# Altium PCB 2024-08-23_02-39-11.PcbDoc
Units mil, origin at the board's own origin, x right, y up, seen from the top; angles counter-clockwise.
Board outline 3261 x 2832 mil, 4 copper layers (Top Layer, MidLayer1, MidLayer2, Bottom Layer); 25 components, 14 nets, 72 pads, 147 vias.
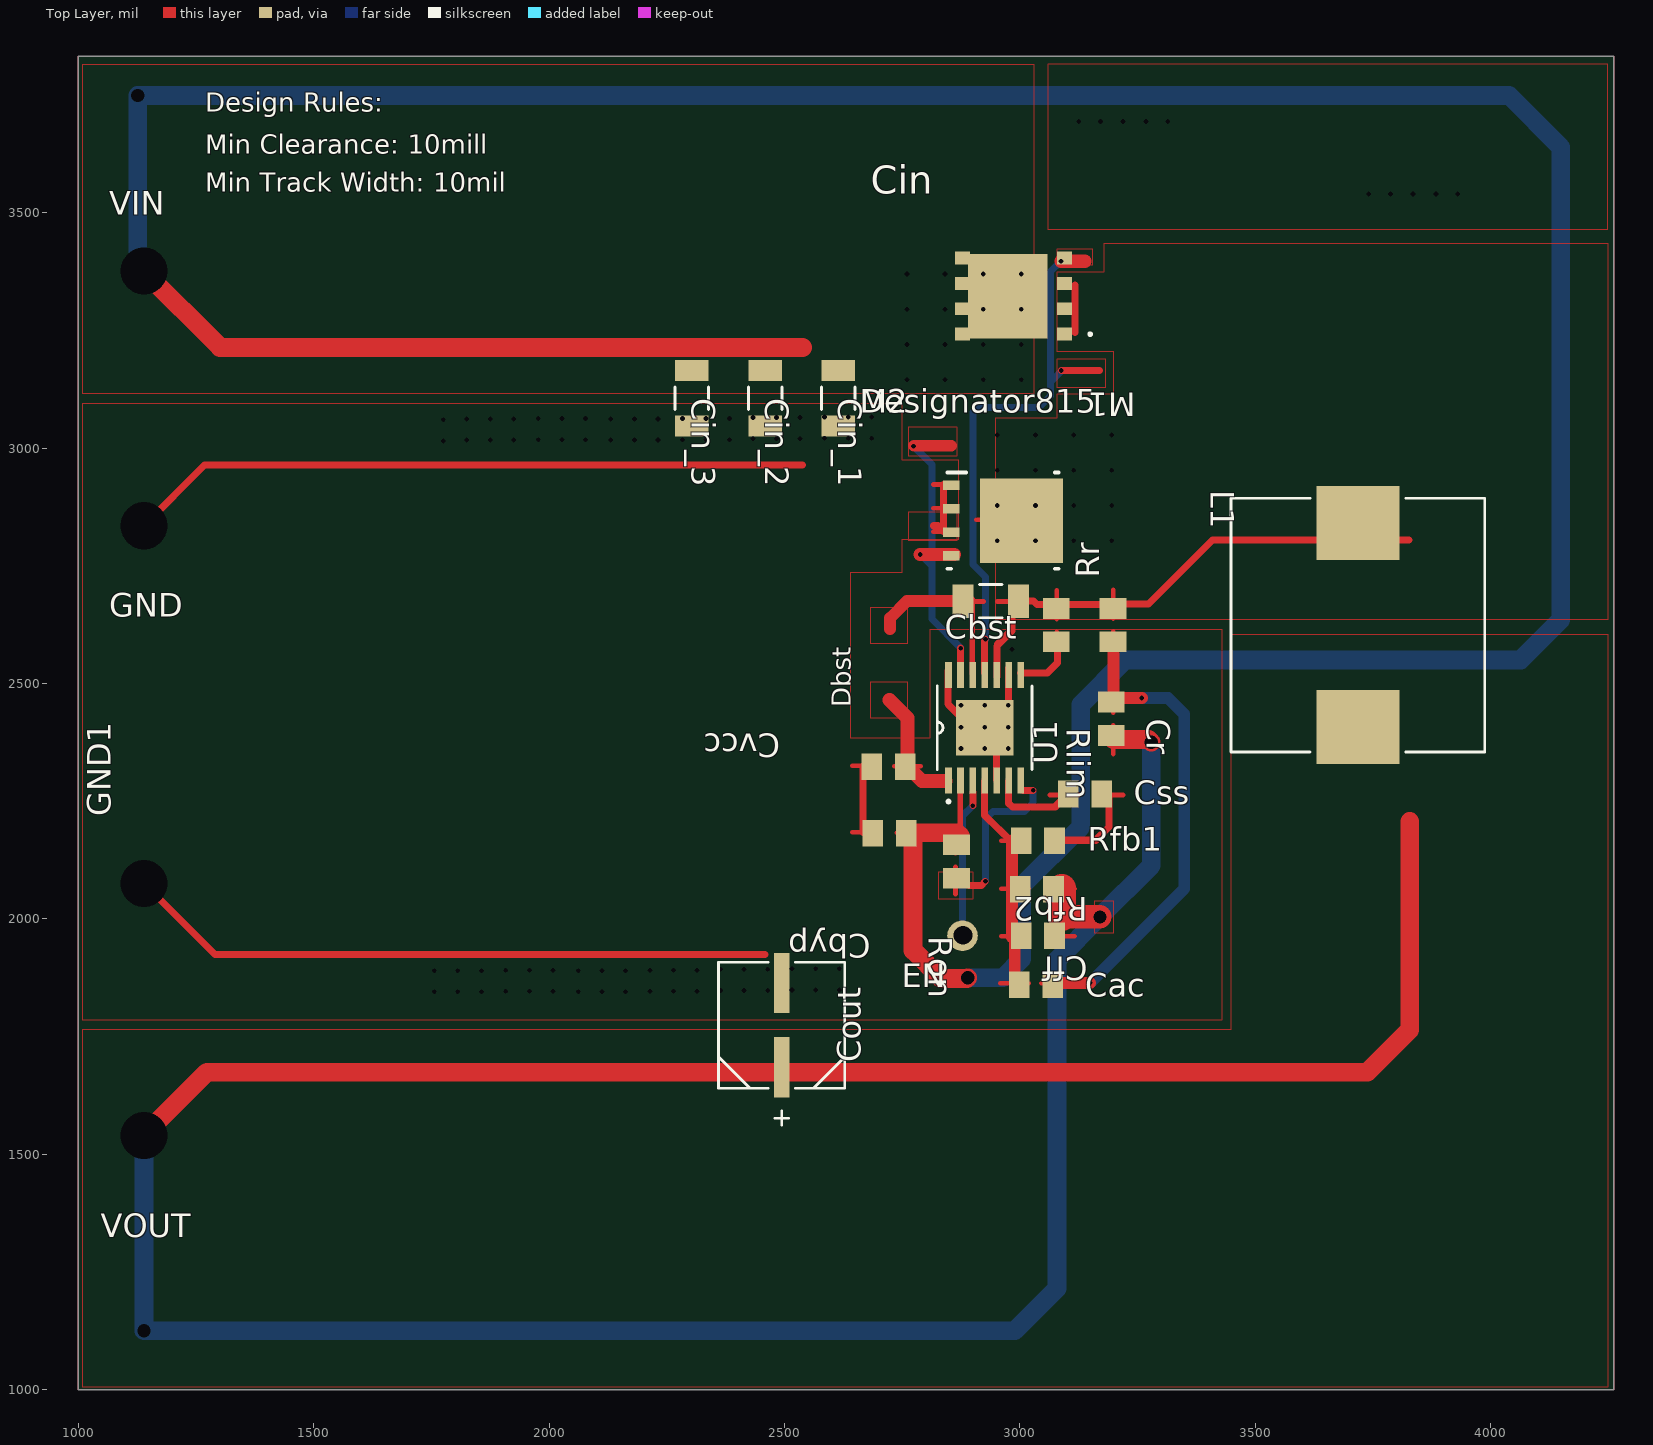
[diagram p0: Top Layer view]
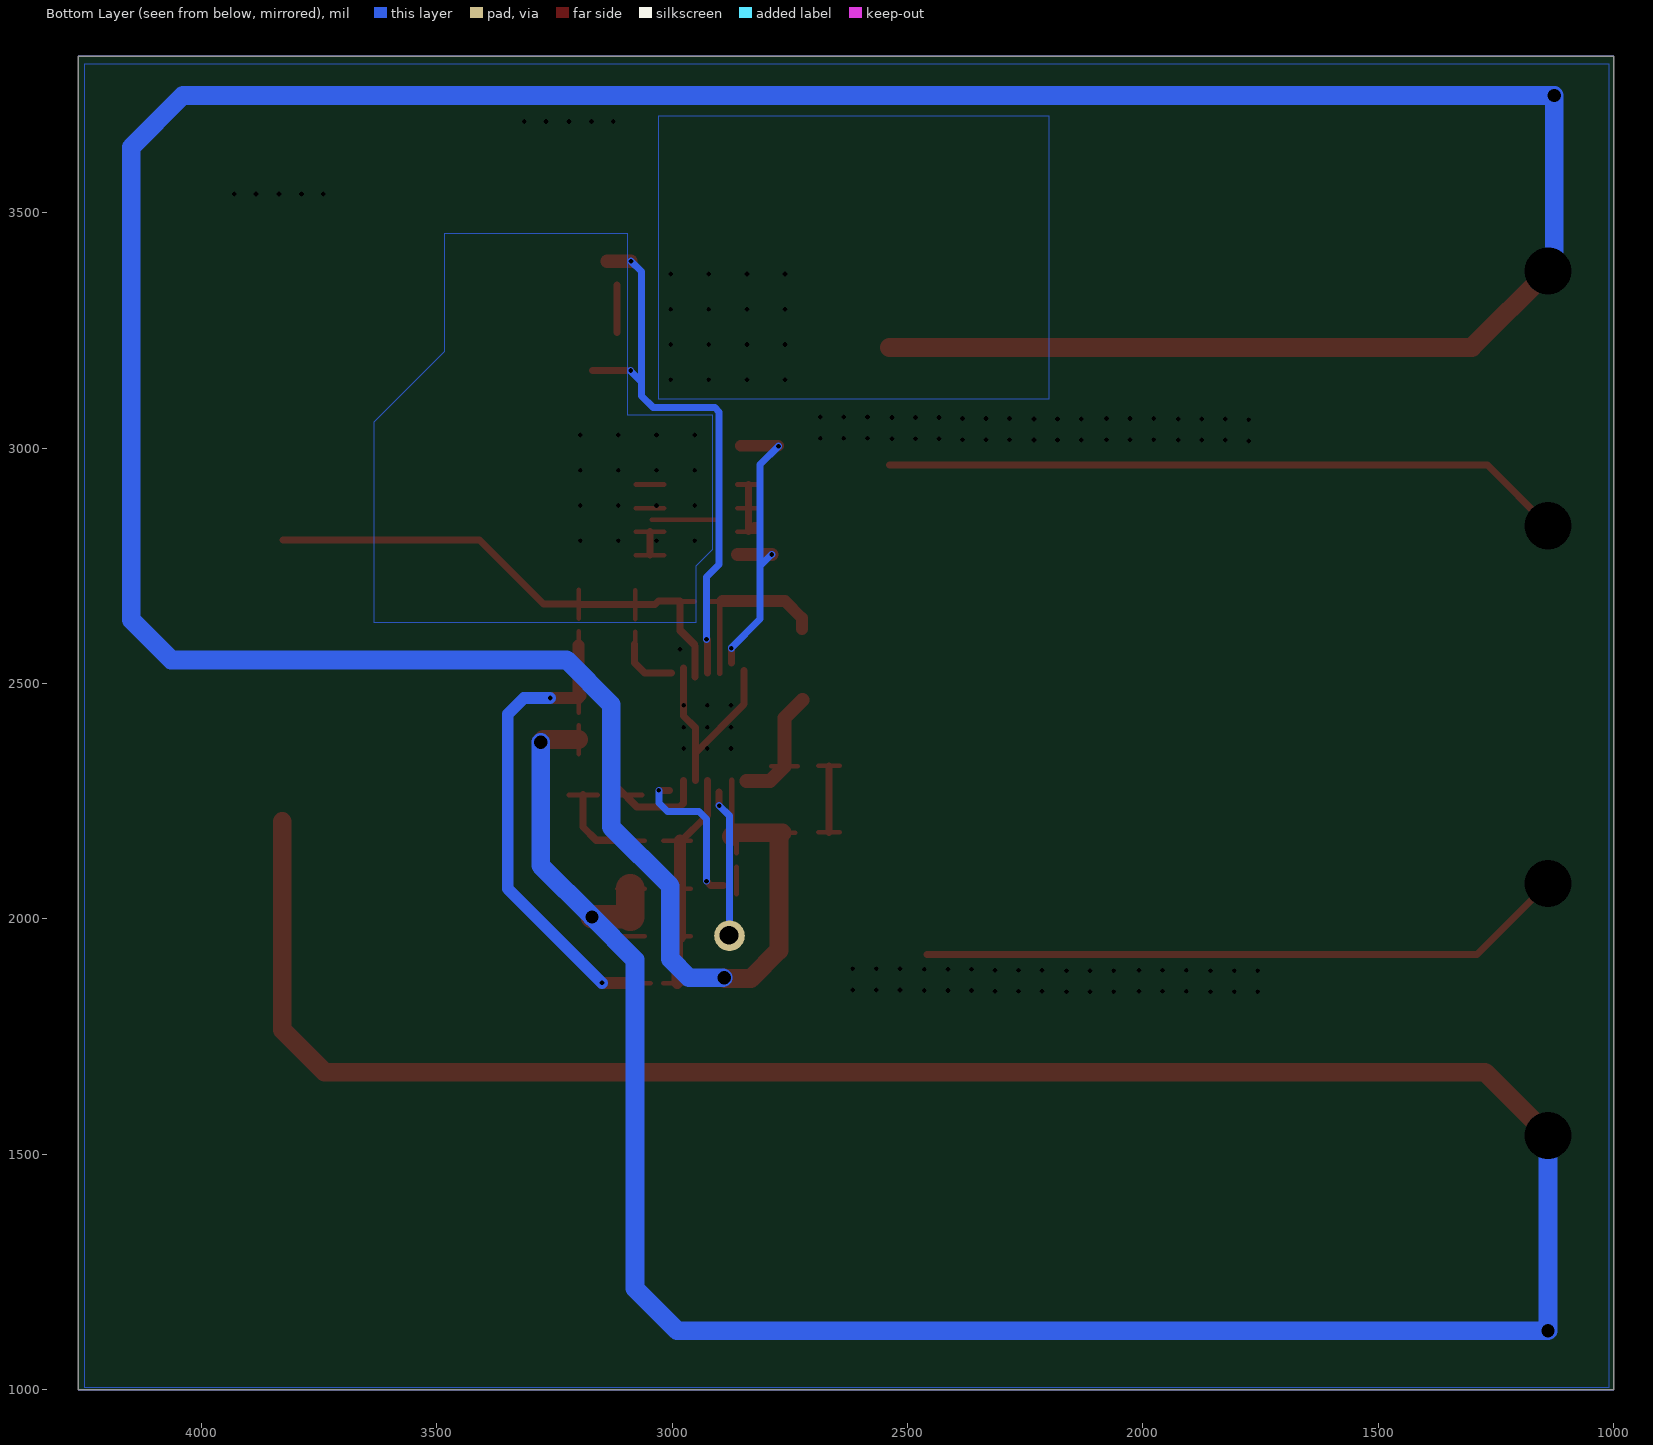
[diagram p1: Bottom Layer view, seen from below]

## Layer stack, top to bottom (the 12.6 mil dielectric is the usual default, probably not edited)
Top Layer: signal copper 1.4
Dielectric: core 12.6, FR-4, Dk 4.8
MidLayer1: signal copper 1.4
Dielectric: prepreg 12.6, FR-4, Dk 4.8
MidLayer2: signal copper 1.4
Dielectric: core 12.6, FR-4, Dk 4.8
Bottom Layer: signal copper 1.4

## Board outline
1000,1000 4261,1000 4261,3832 1000,3832

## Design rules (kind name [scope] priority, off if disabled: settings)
PlaneConnect [All] p0: scope1count=1 scope1_0_kind=Board scope1_0_value=Board scope2count=1 scope2_0_kind=Board scope2_0_value=Board commentlength=0 planeconnectstyle=Direct reliefexpansion=20 reliefentries=4 reliefconductorwidth=10 reliefairgap=10
PlaneConnect [All] p1: planeconnectstyle=Direct reliefexpansion=20 reliefentries=4 reliefconductorwidth=10 reliefairgap=10
PolygonConnect [All] p0: scope1count=1 scope1_0_kind=Board scope1_0_value=Board scope2count=1 scope2_0_kind=Board scope2_0_value=Board commentlength=0 connectstyle=Direct reliefconductorwidth=10 reliefentries=4 polygonreliefangle="90 Angle"
PolygonConnect [All] p1: connectstyle=Direct reliefconductorwidth=10 reliefentries=4 polygonreliefangle="90 Angle"

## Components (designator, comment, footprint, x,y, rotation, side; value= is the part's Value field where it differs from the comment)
Cac "" 0805 3034,1860 r0 top
Cbst "" 1206 2938,2675 r0 top
Cbyp "" 0805 2723,2182 r180 top
Cff "" 0805 3038,1964 r180 top
Cin_1 "" 1206 2614,3106 r270 top
Cin_2 "" 1206 2459,3106 r270 top
Cin_3 "" 1206 2303,3106 r270 top
Cout "" CAPSMT_62_C10 2494,1774 r90 top
Cr "" 0805 3194,2425 r270 top
Css "" 0805 3138,2265 r0 top
Cvcc "" 0805 2721,2323 r180 top
EN "" TP-1502 2878,1964 r0 top
GND "" TP-1502 1138,2834 r0 top
GND1 "" TP-1502 1138,2073 r90 top
L1 "" SRP1270 3718,2624 r270 top
M1 "" TRANS_NexFET_Q5A 2986,3323 r180 top
M2 "" DQJ0008A 2964,2846 r0 top
Rfb1 "" 0805 3038,2166 r0 top
Rfb2 "" 0805 3036,2063 r180 top
Rlim "" 0805 3077,2624 r270 top
Ron "" 0805 2865,2122 r270 top
Rr "" 0805 3198,2624 r90 top
U1 "" MXA14A 2925,2406 r90 top
VIN "" TP-1502 1138,3375 r0 top
VOUT "" TP-1502 1138,1538 r0 top

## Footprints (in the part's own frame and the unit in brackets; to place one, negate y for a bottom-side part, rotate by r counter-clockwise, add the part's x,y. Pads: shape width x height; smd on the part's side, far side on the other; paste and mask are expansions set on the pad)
0805 [mil]
  rect 44x57 smd: 1(-35.5,0) 2(35.5,0)
1206 [mil]
  rect 44x71 smd: 1(-59,0) 2(59,0)
  silkscreen extent -24,-36 24,36
CAPSMT_62_C10 [mil]
  rect 128x32 smd: 1(-89.5,0) 2(89.5,0)
  silkscreen extent -212,-134 134,134
DQJ0008A [mm]
  rect 0.91x0.51 smd: 1(-2.795,1.905) 2(-2.795,0.635) 3(-2.795,-0.635) 4(-2.795,-1.905) 5(2.795,-1.905) 6(2.795,-0.635) 7(2.795,0.635) 8(2.795,1.905)
  rect 4.49x4.57 smd: 9(1.005,0)
  silkscreen extent -3,-2.6 3,2.6
MXA14A [mil]
  rect 56x14 smd: 1(-112,76.77) 2(-112,51.18) 3(-112,25.59) 4(-112,0) 5(-112,-25.59) 6(-112,-51.18) 7(-112,-76.77) 8(112,-76.77) 9(112,-51.18) 10(112,-25.59) 11(112,0) 12(112,25.59) 13(112,51.18) 14(112,76.77)
  rect 118x122 smd: 15(0,0)
  silkscreen extent -160,-100 88,100
SRP1270 [mil]
  rect 157.5x177 smd: 1(-216.75,0) 2(216.75,0)
  silkscreen extent -270,-270 270,270
TP-1502 [mil]
  round 65 hole 32: 1(0,0)
TRANS_NexFET_Q5A [mm]
  rect 0.8x0.7 smd: 1(-2.752,2.055) 2(-2.752,0.685) 3(-2.752,-0.685) 4(-2.752,-2.055) 5(2.752,-2.055) 6(2.752,-0.685) 7(2.752,0.685) 8(2.752,2.055)
  rect 4.3x4.56 smd: 9(0.3,0)
  silkscreen extent -4.22,1.98 -4.07,2.13

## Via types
v1: diameter 0, hole 10, Top Layer to Bottom Layer, 137 vias
v2: diameter 0, hole 28, Top Layer to Bottom Layer, 5 vias
v3: diameter 0, hole 100, Top Layer to Bottom Layer, 4 vias
v4: diameter 0, hole 40, Top Layer to Bottom Layer, 1 vias

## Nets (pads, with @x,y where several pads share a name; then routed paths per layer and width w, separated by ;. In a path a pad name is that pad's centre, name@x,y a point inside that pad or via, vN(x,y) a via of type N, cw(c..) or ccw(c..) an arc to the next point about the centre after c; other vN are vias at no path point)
0: Cbyp.2 Cin_1.2 Cin_2.2 Cin_3.2 Cout.2 Css.2 Cvcc.2 GND1.1 GND.1 M2.1 M2.2 M2.3 Rfb1.2 U1.5 U1.9 U1.14 U1.15 | length 4097
  Top Layer w10: 2644,2184 Cbyp.2@2689,2184 ; 2644,2325 Cvcc.2@2689,2325 ; 2816,2822.5 M2.3@2861,2822.5 ; 2816,2872.5 M2.2@2861,2872.5 ; 2816,2922.5 M2.1@2861,2922.5 ; Rfb1.2@3058,2166 3116,2166 ; Css.2@3158,2263 3219,2263
  Top Layer w15: v3(1139,2075) 1290,1924 2458,1924 ; v3(1139,2835) 1268,2964 2538,2964 ; Cbyp.2@2667,2184 Cvcc.2@2667,2325 ; 2816,2835 2826,2835 2838,2823 2838,2873 M2.1@2838,2923 ; U1.14@2847,2528 2847,2456 U1.15@2950,2352 ; U1.5@2950,2294 U1.15@2950,2352 ; U1.9@2976,2533 2976,2431 2950,2406 U1.15@2950,2352 ; Rfb1.2@3087,2167 3161,2167 3189,2195 Css.2@3189,2264
  other v1: 1756,1845 1806,1845 1856,1845 2062,1845 2112,1845 2162,1845 1908,1846 1958,1846 2008,1846 2214,1846 2264,1846 2314,1846 2364,1848 2414,1848 2464,1848 2516,1849 2566,1849 2616,1849 1756,1890 1806,1890 1856,1890 2062,1890 2112,1890 2162,1890 1908,1891 1958,1891 2008,1891 2214,1891 2264,1891 2314,1891 2364,1893 2414,1893 2464,1893 2516,1894 2566,1894 2616,1894 2875,2362 2925,2362 2975,2362 2875,2407 2925,2407 2975,2407 2875,2454 2925,2454 2975,2454 2983,2573 1775,3015 1825,3017 1875,3017 1925,3017 2131,3017 2181,3017 2231,3017 1977,3018 2027,3018 2077,3018 2283,3018 2333,3018 2383,3018 2433,3020 2483,3020 2533,3020 2585,3021 2635,3021 2685,3021 1775,3060 1825,3062 1875,3062 1925,3062 2131,3062 2181,3062 2231,3062 1977,3063 2027,3063 2077,3063 2283,3063 2333,3063 2383,3063 2433,3065 2483,3065 2533,3065 2585,3066 2635,3066 2685,3066 3741,3540 3787,3540 3835,3540 3884,3540 3930,3540 3125,3694 3171,3694 3219,3694 3268,3694 3314,3694
1: Cbyp.1 Cin_1.1 Cin_2.1 Cin_3.1 M1.5 M1.6 M1.7 M1.8 M1.9 Ron.1 U1.2 VIN.1 | length 8469.1
  Top Layer w10: Cbyp.1@2738,2183 2794,2183 ; Ron.1@2863,2140 2863,2198
  Top Layer w12: 2866,2183 2873,2190 U1.2@2873,2294
  Top Layer w40: v3(1139,3376) 1301,3214 2538,3214 ; Ron.1@2874,2175 2866,2183 2766,2183 2769,2180 2773,2180 2773,1933 2833,1873 2887,1873 v2(2889,1875)
  Bottom Layer w40: VIN.1@1139,3375 1126,3388 v2(1126,3749) 4039,3749 4149,3639 4149,2635 4064,2550 3224,2550 3129,2455 3129,2195 3004,2070 3004,1915 2964,1875 2892,1875
  other v1: 2760,3145 2841,3145 2922,3145 3003,3145 2760,3220 2841,3220 2922,3220 3003,3220 2760,3295 2841,3295 2922,3295 3003,3295 2760,3370 2841,3370 2922,3370 3003,3370
2: Ron.2 U1.7 | length 393.4
  Top Layer w10: 2863,2052 2863,2110
  Top Layer w15: Ron.2@2891,2071 2918,2071 2926,2079 ; U1.7@3005,2273 v1(3028,2273)
  Bottom Layer w15: v1(2927,2080) 2927,2212 2943,2228 3010,2228 3028,2246 v1(3028,2273)
3: Cac.1 Cff.2 Rfb1.1 Rfb2.2 U1.4 | length 697.7
  Top Layer w10: 2958,1863 Cac.1@3019,1863 ; 2960,1963 Cff.2@3018,1963 ; 2960,2064 Rfb2.2@3018,2064 ; 2960,2166 Rfb1.1@3018,2166
  Top Layer w15: U1.4 2925,2293 2925,2220 Rfb1.1@2983,2163
  Top Layer w25: Rfb1.1@2983,2167 2983,2163 2983,1961 Cff.2@2984,1960 ; Cac.1@2989,1864 Cff.2@2989,1964
4: Cbst.2 L1.1 M1.1 M1.2 M1.3 M2.5 M2.6 M2.7 M2.8 M2.9 Rlim.1 Rr.2 U1.10 | length 1829.7
  Top Layer w10: 2907,2847.5 M2.9@3043,2847.5 ; 2952,2674 Cbst.2@3013,2674 ; M2.9@3017,2772.5 M2.5@3077,2772.5 ; M2.9@3017,2822.5 M2.6@3077,2822.5 ; M2.9@3017,2872.5 M2.7@3077,2872.5 ; M2.9@3017,2922.5 M2.8@3077,2922.5 ; 3078,2637 3078,2698 ; Rr.2@3198,2638 3198,2699
  Top Layer w15: U1.10@2951,2514 2951,2580 2983,2612 2983,2615 ; 2952,2584 2983,2615 ; M2.9@3047,2773 M2.9@3047,2823 ; 3117,3246 3117,3296 3117,3346 ; 3826,2805 3409,2805 3273,2669 3199,2669 3198,2668 3079,2668 3036,2668 3029,2675 2983,2675 2983,2615
  other v1: 2952,2803 3033,2803 3114,2803 3195,2803 2952,2878 3033,2878 3114,2878 3195,2878 2952,2953 3033,2953 3114,2953 3195,2953 2952,3028 3033,3028 3114,3028 3195,3028
5: Cff.1 Cout.1 Cr.2 L1.2 Rfb2.1 VOUT.1 | length 7261.4
  Top Layer w10: Cff.1@3058,1963 3116,1963 ; Rfb2.1@3058,2064 3116,2064 ; 3198,2350 Cr.2@3198,2411
  Top Layer w40: v3(1139,1540) 1273,1674 2458,1674 3738,1674 3828,1764 3828,2207 ; Cr.2@3199,2381 3273,2381 v2(3279,2375)
  Top Layer w50: 3089,2004 v2(3170,2004)
  Top Layer w60: 3089,2004 Rfb2.1@3089,2065
  Bottom Layer w40: v3(1139,1540) v2(1139,1125) 2989,1125 3079,1215 3079,1913 v2(3170,2004) 3279,2113 v2(3279,2375)
6: M2.4 U1.13 | length 734.4
  Top Layer w10: 2816,2772.5 M2.4@2861,2772.5
  Top Layer w15: U1.13@2874,2544 v1(2874,2575)
  Top Layer w25: 2775,3005 2854,3005
  Top Layer w28: v1(2788,2774) M2.4@2861,2774
  Bottom Layer w15: v1(2774,3004) 2813,2965 2813,2750 ; v1(2788,2774) 2789,2774 2813,2750 ; 2874,2574 2874,2576 2813,2637 2813,2750
7: Cbst.1 U1.12 | length 418.1
  Top Layer w10: Cbst.1@2867,2674 2923,2674
  Top Layer w12: Cbst.1@2893,2675 2899,2668 U1.12@2899,2522
  Top Layer w25: 2724,2616 2724,2639 2760,2675 Cbst.1@2893,2675
8: M1.4 U1.11 | length 1204.9
  Top Layer w15: U1.11@2925,2522 2925,2593 2926,2594 ; v1(3088,3165) 3169,3165
  Top Layer w28: v1(3087,3397) 3138,3397
  Bottom Layer w15: v1(2927,2594) 2927,2726 2900,2753 2900,3077 2909,3086 3040,3086 3065,3111 3065,3375 v1(3087,3397) ; 3066,3142 3088,3164 v1(3088,3165)
9: Rlim.2 U1.8 | length 189.1
  Top Layer w10: 3078,2549 Rlim.2@3078,2610
  Top Layer w15: U1.8@3001,2522 3058,2522 3080,2544 Rlim.2@3080,2584
10: Css.1 U1.6 | length 268.2
  Top Layer w10: 3064,2263 3125,2263
  Top Layer w15: U1.6@2976,2294 2976,2245 2984,2238 3075,2238 Css.1@3115,2278
11: Cvcc.1 U1.1 | length 304.6
  Top Layer w10: 2733,2324 2789,2324
  Top Layer w30: 2723,2465 2761,2427 Cvcc.1@2761,2326 ; Cvcc.1@2761,2324 2792,2293 U1.1@2842,2293
18: EN.1 U1.3 | length 318.1
  Top Layer w15: 2900,2241 U1.3@2900,2269
  Bottom Layer w15: EN.1@2878,1960 2878,2219 2900,2241
  other v1: 2900,2240
  other v4: 2879,1965
25: Cac.2 Cr.1 Rr.1 | length 1182
  Top Layer w10: 3046,1863 3107,1863 ; 3198,2438 3198,2499 ; 3198,2550 3198,2611
  Top Layer w25: Cac.2@3077,1864 v1(3149,1864) ; Cr.1@3194,2474 3199,2479 Rr.1@3199,2581 ; Cr.1@3199,2469 v1(3259,2469)
  Bottom Layer w25: v1(3149,1864) 3349,2064 3349,2435 3315,2469 v1(3259,2469)

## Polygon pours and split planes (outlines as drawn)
2 on Top Layer " " (solid, pour order 0): 2827,2042 2827,2100 2900,2100 2900,2042
11 on Top Layer " " (solid, pour order 1): 2683,2426 2683,2504 2761,2504 2761,2426
7 on Top Layer " " (solid, pour order 2): 2683,2584 2683,2662 2761,2662 2761,2584
6 on Top Layer " " (solid, pour order 3): 2764,2983 2764,3045 2866,3045 2866,2983
8 on Top Layer " " (solid, pour order 4): 3079,3128 3079,3190 3181,3190 3181,3128
8 on Top Layer " " (solid, pour order 5): 3079,3388 3079,3423 3154,3423 3154,3388
1 on Top Layer " " (solid, pour order 6): 2906,3244 2906,3397 3056,3397 3056,3244
4 on Top Layer " " (solid, pour order 7): 2949,2635 2949,3065 3079,3065 3079,3115 3199,3115 3199,3205 3079,3205 3079,3375 3179,3375 3179,3435 4249,3435 4249,2635
1 on Top Layer " " (solid, pour order 8): 1009,3815 3029,3815 3029,3115 1009,3115
5 on Top Layer " " (solid, pour order 9): 1009,1005 1009,1765 3449,1765 3449,2605 4249,2605 4249,1005
5 on Top Layer " " (solid, pour order 10): 3158,2037 3158,1971 3199,1971 3199,2037
0 on Top Layer " " (solid, pour order 13): 2764,2803 2764,2865 2866,2865 2866,2803
0 on Top Layer " " (solid, pour order 14): 3059,3815 3059,3465 4249,3465 4249,3815
0 on Top Layer " " (solid, pour order 15): 1009,3095 2749,3095 2749,2975 2869,2975 2869,2805 2749,2805 2749,2735 2639,2735 2639,2385 2809,2385 2809,2615 3429,2615 3429,1785 1009,1785
4 on Bottom Layer " " (solid, pour order 11): 3094,3455 3484,3455 3484,3205 3634,3055 3634,2630 2949,2630 2949,2750 2914,2785 2914,3070 3094,3070 3094,3390
1 on Bottom Layer " " (solid, pour order 12): 2199,3705 3029,3705 3029,3105 2199,3105
0 on Bottom Layer " " (solid, pour order 16): 1009,1005 1009,3815 4249,3815 4249,1005
no net on Top Paste "Top Layer-No Net" (solid, remove dead copper): 2893.38,3228.31 2893.38,3255.87 2861.89,3255.87 2861.89,3228.31
no net on Top Solder "Top Layer-No Net" (solid, remove dead copper): 3110.11,3228.32 3110.11,3255.87 3078.62,3255.87 3078.62,3228.32
no net on Top Solder "Top Layer-No Net" (solid, remove dead copper): 3110.11,3282.25 3110.11,3309.81 3078.62,3309.81 3078.62,3282.25
no net on Top Solder "Top Layer-No Net" (solid, remove dead copper): 3110.11,3336.19 3110.11,3363.75 3078.62,3363.75 3078.62,3336.19
no net on Top Solder "Top Layer-No Net" (solid, remove dead copper): 3110.11,3390.13 3110.11,3417.69 3078.62,3417.69 3078.62,3390.13
no net on Top Solder "Top Layer-No Net" (solid, remove dead copper): 2893.38,3390.13 2893.38,3417.68 2861.89,3417.68 2861.89,3390.13
no net on Top Solder "Top Layer-No Net" (solid, remove dead copper): 2893.38,3336.19 2893.38,3363.75 2861.89,3363.75 2861.89,3336.19
no net on Top Solder "Top Layer-No Net" (solid, remove dead copper): 2893.38,3282.25 2893.38,3309.81 2861.89,3309.81 2861.89,3282.25
no net on Top Solder "Top Layer-No Net" (solid, remove dead copper): 2893.38,3228.31 2893.38,3255.87 2861.89,3255.87 2861.89,3228.31
no net on Top Solder "Top Layer-No Net" (solid, remove dead copper): 2893.48,3233.24 3062.77,3233.24 3062.77,3412.76 2893.48,3412.76
no net on Top Solder "Top Layer-No Net" (solid, remove dead copper): 3052.58,2812.93 3061.44,2812.93 3061.44,2829.07 3052.58,2829.07
no net on Top Solder "Top Layer-No Net" (solid, remove dead copper): 3052.58,2762.93 3061.44,2762.93 3061.44,2779.07 3052.58,2779.07
no net on Top Solder "Top Layer-No Net" (solid, remove dead copper): 3052.58,2912.93 3061.44,2912.93 3061.44,2929.07 3052.58,2929.07
no net on Top Solder "Top Layer-No Net" (solid, remove dead copper): 3052.58,2862.93 3061.44,2862.93 3061.44,2879.07 3052.58,2879.07
no net on Top Paste "Top Layer-No Net" (solid, remove dead copper): 2917.94,2823.36 2917.94,2868.64 2917.97,2869.02 2918.09,2869.39 2918.27,2869.73 2918.51,2870.03 2918.81,2870.27 2919.15,2870.46 2919.52,2870.57 2919.91,2870.61 2978.17,2870.61 2978.56,2870.57 2978.93,2870.46 2979.27,2870.27 2979.57,2870.03 2979.81,2869.73 2979.99,2869.39 2980.1,2869.02 2980.14,2868.64 2980.14,2823.36 2980.1,2822.98 2979.99,2822.61 2979.81,2822.27 2979.57,2821.97 2979.27,2821.73 2978.93,2821.54 2978.56,2821.43 2978.17,2821.39 2919.91,2821.39 2919.52,2821.43 2919.15,2821.54 2918.81,2821.73 2918.51,2821.97 2918.27,2822.27 2918.09,2822.61 2917.97,2822.98
no net on Top Paste "Top Layer-No Net" (solid, remove dead copper): 3050.22,2868.64 3050.22,2823.36 3050.18,2822.98 3050.07,2822.61 3049.89,2822.27 3049.64,2821.97 3049.35,2821.73 3049.01,2821.54 3048.64,2821.43 3048.25,2821.39 2989.98,2821.39 2989.6,2821.43 2989.23,2821.54 2988.89,2821.73 2988.59,2821.97 2988.35,2822.27 2988.17,2822.61 2988.05,2822.98 2988.02,2823.36 2988.02,2868.64 2988.05,2869.02 2988.17,2869.39 2988.35,2869.73 2988.59,2870.03 2988.89,2870.27 2989.23,2870.46 2989.6,2870.57 2989.98,2870.61 3048.25,2870.61 3048.64,2870.57 3049.01,2870.46 3049.35,2870.27 3049.64,2870.03 3049.89,2869.73 3050.07,2869.39 3050.18,2869.02
no net on Top Paste "Top Layer-No Net" (solid, remove dead copper): 3050.22,2925.72 3050.22,2880.45 3050.18,2880.06 3050.07,2879.7 3049.89,2879.36 3049.64,2879.06 3049.35,2878.81 3049.01,2878.63 3048.64,2878.52 3048.25,2878.48 2989.98,2878.48 2989.6,2878.52 2989.23,2878.63 2988.89,2878.81 2988.59,2879.06 2988.35,2879.36 2988.17,2879.7 2988.05,2880.06 2988.02,2880.45 2988.02,2925.72 2988.05,2926.11 2988.17,2926.48 2988.35,2926.82 2988.59,2927.12 2988.89,2927.36 2989.23,2927.54 2989.6,2927.66 2989.98,2927.69 3048.25,2927.69 3048.64,2927.66 3049.01,2927.54 3049.35,2927.36 3049.64,2927.12 3049.89,2926.82 3050.07,2926.48 3050.18,2926.11
no net on Top Paste "Top Layer-No Net" (solid, remove dead copper): 2917.94,2880.45 2917.94,2925.72 2917.97,2926.11 2918.09,2926.48 2918.27,2926.82 2918.51,2927.12 2918.81,2927.36 2919.15,2927.54 2919.52,2927.66 2919.91,2927.69 2978.17,2927.69 2978.56,2927.66 2978.93,2927.54 2979.27,2927.36 2979.57,2927.12 2979.81,2926.82 2979.99,2926.48 2980.1,2926.11 2980.14,2925.72 2980.14,2880.45 2980.1,2880.06 2979.99,2879.7 2979.81,2879.36 2979.57,2879.06 2979.27,2878.81 2978.93,2878.63 2978.56,2878.52 2978.17,2878.48 2919.91,2878.48 2919.52,2878.52 2919.15,2878.63 2918.81,2878.81 2918.51,2879.06 2918.27,2879.36 2918.09,2879.7 2917.97,2880.06
no net on Top Paste "Top Layer-No Net" (solid, remove dead copper): 2917.94,2766.28 2917.94,2811.55 2917.97,2811.94 2918.09,2812.3 2918.27,2812.64 2918.51,2812.94 2918.81,2813.19 2919.15,2813.37 2919.52,2813.48 2919.91,2813.52 2978.17,2813.52 2978.56,2813.48 2978.93,2813.37 2979.27,2813.19 2979.57,2812.94 2979.81,2812.64 2979.99,2812.3 2980.1,2811.94 2980.14,2811.55 2980.14,2766.28 2980.1,2765.89 2979.99,2765.52 2979.81,2765.18 2979.57,2764.88 2979.27,2764.64 2978.93,2764.46 2978.56,2764.34 2978.17,2764.31 2919.91,2764.31 2919.52,2764.34 2919.15,2764.46 2918.81,2764.64 2918.51,2764.88 2918.27,2765.18 2918.09,2765.52 2917.97,2765.89
no net on Top Paste "Top Layer-No Net" (solid, remove dead copper): 3050.22,2811.55 3050.22,2766.28 3050.18,2765.89 3050.07,2765.52 3049.89,2765.18 3049.64,2764.88 3049.35,2764.64 3049.01,2764.46 3048.64,2764.34 3048.25,2764.31 2989.98,2764.31 2989.6,2764.34 2989.23,2764.46 2988.89,2764.64 2988.59,2764.88 2988.35,2765.18 2988.17,2765.52 2988.05,2765.89 2988.02,2766.28 2988.02,2811.55 2988.05,2811.94 2988.17,2812.3 2988.35,2812.64 2988.59,2812.94 2988.89,2813.19 2989.23,2813.37 2989.6,2813.48 2989.98,2813.52 3048.25,2813.52 3048.64,2813.48 3049.01,2813.37 3049.35,2813.19 3049.64,2812.94 3049.89,2812.64 3050.07,2812.3 3050.18,2811.94
no net on Top Solder "Top Layer-No Net" (solid, remove dead copper): 2917.15,2760.06 2917.15,2931.94 2917.19,2932.34 2917.31,2932.72 2917.5,2933.08 2917.75,2933.39 2918.06,2933.65 2918.42,2933.84 2918.8,2933.95 2919.2,2933.99 3052.1,2933.99 3052.5,2933.95 3052.89,2933.84 3053.24,2933.65 3053.56,2933.39 3053.81,2933.08 3054,2932.72 3054.12,2932.34 3054.16,2931.94 3054.16,2760.06 3054.12,2759.66 3054,2759.28 3053.81,2758.92 3053.56,2758.61 3053.24,2758.35 3052.89,2758.16 3052.5,2758.05 3052.1,2758.01 2919.2,2758.01 2918.8,2758.05 2918.42,2758.16 2918.06,2758.35 2917.75,2758.61 2917.5,2758.92 2917.31,2759.28 2917.19,2759.66

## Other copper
Multi-Layer:
  the board outline again, w1

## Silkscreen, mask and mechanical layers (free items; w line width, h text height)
Top Overlay:
  text "Design Rules:" at 1269,3715 h40
  text "Min Clearance: 10mill" at 1269,3625 h40
  text "Min Track Width: 10mil" at 1269,3545 h40
  text "Cin" at 2683,3540 h60
  text "Dbst" at 2641,2449 h40 r90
